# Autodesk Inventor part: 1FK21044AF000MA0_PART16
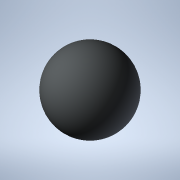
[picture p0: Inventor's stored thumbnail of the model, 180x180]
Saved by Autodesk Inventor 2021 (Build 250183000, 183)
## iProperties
Created: 2025-04
Part Number: 1FK21044AF000MA0_PART16
Material: Generic
Catalog Web Link: www.3dfindit.com
Description: -Servo synchronous motor
Document SubType Name: Modeling
Designer: psAdmin
Mass: 0.137258 g
Surface Area: 1.2868 cm^2
Volume: 0.137258 cm^3
Density: 1 g/cm^3
Appearance: PSOLRGB-212-217-219
Category: PARTsolutions
Title: 1FK21044AF000MA0_PART16
Author: Cadenas PARTsolutions
Comments: Servo synchronous motor
Sending System: PARTsolutions
Preprocessor: ST-DEVELOPER v19.3
PSOL_IDENT_0: {$CADENAS_DATA/23d-libs/siemens_ag/_cat_/39/c4/1fk21044af000ma0.prj},216 {VTYP=3D},{NB=1FK21044AF000
PSOL_IDENT_1: MA0_PART16},{LINA=1FK21044AF000MA0_PART16},{NN=1FK21044AF000MA0_PART16},{NOPRJ=TRUE},{DATE=19.08.202
PSOL_IDENT_2: 5 14:00:33},{GEOMDATE=30.07.2025 02:02:22},{VERSION=},{LINEID=10},{WBVAR=},{WBNUMERIC=}  {NB=1FK2104
PSOL_IDENT_3: 4AF000MA0_PART16},{LINA=1FK21044AF000MA0_PART16},{KT=DUMMY},{PREVIEW=../../../_pool_/cb/72/p_d211_xx
PSOL_IDENT_4: _00434j.png},{DESCSHORT=SIMOTICS S-1FK2 HD, SINAMICS S210 3AC 400V-480V, 1.27 Nm, 3000 rpm},{DESCLON
PSOL_IDENT_5: G=SIMOTICS S-1FK2 HD servo motor M0=1.27 Nm; PN = 0.4 kW at nN=3000 rpm (380-480 V); PN = 0.2 kW at
PSOL_IDENT_6: nN=1500 rpm (200-240 V); degree of protection IP64; cylindrical shaft D19x40mm; absolute encoder 22-
PSOL_IDENT_7: bit + 12-bit multiturn (encoder AM22DQC); with OCC interface; plug size M17, rotatable; SIMOTICS S-1
PSOL_IDENT_8: FK2 servomotorfor a wide range of uses in industrial environments. SIMOTICS S‑1FK2 servomotors are c
PSOL_IDENT_9: ompact synchronous motors with a high dynamic performance that set themselves apart as a result of t
PSOL_IDENT_10: heir high power density, degree of protection and overload capability. The motors are available in t
PSOL_IDENT_11: wo variants: as High Dynamic variant (highest dynamic performance as a result of the low intrinsic m
PSOL_IDENT_12: oment of inertia for applications demanding a high dynamic performance with low moved masses) - and
PSOL_IDENT_13: as Compact variant (precise and stable closed-loop control for medium up to large moved masses as a
PSOL_IDENT_14: result of a medium intrinsic moment of inertia). SIMOTICSS‑1FK2 servomotors fully exploit their stre
PSOL_IDENT_15: ngths in a system with the SINAMICSS210 frequency converter and simple connection using the one cabl
PSOL_IDENT_16: e connection (OCC). Advantages include the short control and positioning times, fast and precise cor
PSOL_IDENT_17: rection of disturbing quantities as well as stable control with a high dynamic performance. The serv
PSOL_IDENT_18: o motors can be configured to address a wide range of requirements. For example with and without hol
PSOL_IDENT_19: ding brake, IP64 or IP65 degree of protection, singleturn or multiturn absolute encoders - to name j
PSOL_IDENT_20: ust a few. Further, the servomotors are available in different shaft heights extending from 20 to 10
PSOL_IDENT_21: 0. A shaft sealing ring is available to achieve an IP65 degree of protection and for subsequent moun
PSOL_IDENT_22: ting at the motor or as spare part. SIMOTICS - the optimum motor for each and every motion control a
PSOL_IDENT_23: pplication.},{INTNO=804766906428},{SUPPLIERALTNO=1FK2104-4AF00-0MA0},{MANUID=1FK21044AF000MA0},{MANU
PSOL_IDENT_24: NAME=Siemens},{MANUTYPEDESC=Synchronous motor 1FK2-HD 1.27 NM},{AAU732=SIMOTICS},{AAO057=S-1FK2},{AA
PSOL_IDENT_25: U734=SIMOTICS S-1FK2 HD servo motor M0=1.27 Nm; PN = 0.4 kW at nN=3000 rpm (380-480 V); PN = 0.2 kW
PSOL_IDENT_26: at nN=1500 rpm (200-240 V); degree of protection IP64; cylindrical shaft D19x40mm; absolute encoder
PSOL_IDENT_27: 22-bit + 12-bit multiturn (encoder AM22DQC); with OCC interface; plug size M17, rotatable;},{AAW338=
PSOL_IDENT_28: Synchronous motor 1FK2-HD 1.27 NM},{AAO742=SIMOTICS},{AAO663=4042948693322},{NOCUPEROU=1},{PRICEQUAN
PSOL_IDENT_29: TITY=1},{QUANTITYMIN=1},{QUANTITYINT=1},{CTN=85015100},{COO=DE},{AAO676=1FK2104-4AF00-0MA0},{AAO677=
PSOL_IDENT_30: Siemens AG},{ORDERUNIT=C62},{CONTENTUNIT=C62}
NB: 1FK21044AF000MA0_PART16
NT: Servo synchronous motor
NBSYN: $MANUID._PART16
LINA: 1FK21044AF000MA0_PART16
CATALOG: SIEMENS
PREVIEW: ../../../_pool_/cb/72/p_d211_xx_00434j.png
DESCSHORT: SIMOTICS S-1FK2 HD, SINAMICS S210 3AC 400V-480V, 1.27 Nm, 3000 rpm
DESCLONG: SIMOTICS S-1FK2 HD servo motor M0=1.27 Nm; PN = 0.4 kW at nN=3000 rpm (380-480 V); PN = 0.2 kW at nN=1500 rpm (200-240 V); degree of protection IP64; cylindrica
INTNO: 804766906428
SUPPLIERALTNO: 1FK2104-4AF00-0MA0
MANUID: 1FK21044AF000MA0
MANUNAME: Siemens
MANUTYPEDESC: Synchronous motor 1FK2-HD 1.27 NM
AAU732: SIMOTICS
AAO057: S-1FK2
AAU734: SIMOTICS S-1FK2 HD servo motor M0=1.27 Nm; PN = 0.4 kW at nN=3000 rpm (380-480 V); PN = 0.2 kW at nN=1500 rpm (200-240 V); degree of protection IP64; cylindrica
AAW338: Synchronous motor 1FK2-HD 1.27 NM
AAO742: SIMOTICS
AAO663: 4042948693322.0
NOCUPEROU: 1
PRICEQUANTITY: 1
QUANTITYMIN: 1
QUANTITYINT: 1
CTN: 85015100
COO: DE
ARTICLENO: 1FK21044AF000MA0_PART16
BOMINFO: 1FK21044AF000MA0_PART16
CREATOR: CADENAS GmbH
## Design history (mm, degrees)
feature "2025_04_17_15_01_28_0038"
body "Solid1"
